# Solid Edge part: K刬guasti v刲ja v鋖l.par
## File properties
Author: Türk
Template: Iso Part.par
Last saved by: Türk
Revision: 18
Application: Solid Edge
Accuracy: 0,990
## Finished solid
Body 1: solid body, 23 faces, 22 edges, 0 vertices.
  Faces by surface: plane 12, cylinder 11
  Edges by curve: circle 22
Bounding box of the edges (mm): 30.000 x 550.000 x 30.000, from (-15, -85, -15) to (15, 465, 15).
Cylindrical faces by radius (mm): R14 x5, R15 x6
Planar faces by outward normal: +y 6, -y 6
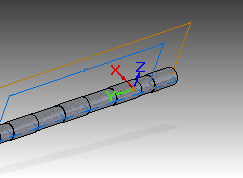
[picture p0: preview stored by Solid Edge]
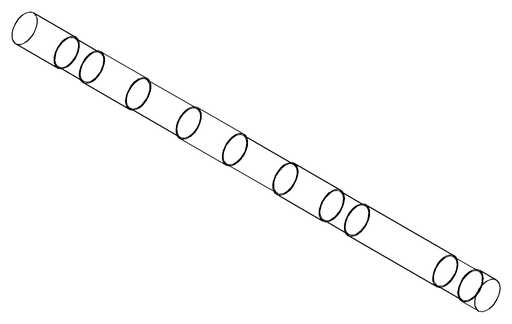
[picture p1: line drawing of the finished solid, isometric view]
